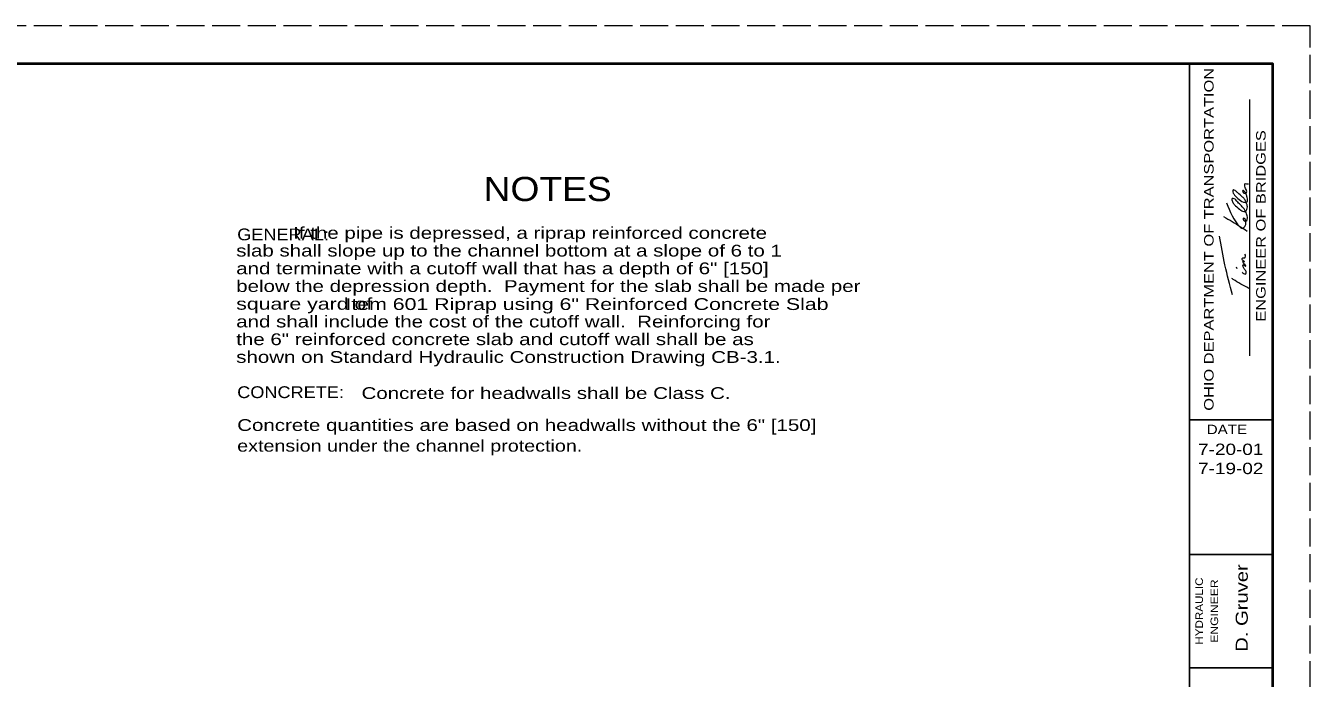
# Model space of a CAD drawing. Extents: x 685.4 to 719.4, y 1059.8 to 1105.8.
# Drawn here: x 702.44 to 719.44, y 1073.13 to 1081.77 of the extents above; entities that cross this region are included whole.
import ezdxf
from ezdxf.enums import TextEntityAlignment as Align

# ---------------------------------------------------------------- set-up
doc = ezdxf.new("R2010")
doc.units = 0
doc.header["$LTSCALE"] = 0.062
doc.linetypes.add('LONG_DASHED', pattern=[7.5, 6, -1.5])
doc.layers.add('1', color=7, linetype='Continuous', lineweight=13)

msp = doc.modelspace()

# ---------------------------------------------------------------- linework, layer by layer
at = {"layer": '1', "lineweight": 25}
for p, q in [((687.44108, 1081.27067), (718.94108, 1081.27067)), ((717.84108, 1060.27067), (717.84108, 1081.27067)), ((718.94108, 1081.27067), (718.94108, 1060.27067)), ((718.94108, 1076.55483), (717.84108, 1076.55483)), ((718.94108, 1074.77067), (717.84108, 1074.77067)), ((718.94108, 1073.27067), (717.84108, 1073.27067))]:
    msp.add_line(p, q, dxfattribs=at)
at = {"layer": '1'}
for p, q in [((718.63983, 1077.40167), (718.63983, 1080.79175)), ((718.47233, 1078.55258), (718.46217, 1078.57183))]:
    msp.add_line(p, q, dxfattribs=at)
at = {"layer": '1', "linetype": 'LONG_DASHED'}
msp.add_lwpolyline([(685.44108, 1059.77067), (719.44108, 1059.77067), (719.44108, 1081.77067), (685.44108, 1081.77067)], close=True, dxfattribs=at)
at = {"layer": '1', "lineweight": 40}
msp.add_lwpolyline([(687.44108, 1081.27067), (718.94108, 1081.27067), (718.94108, 1060.27067), (687.44108, 1060.27067)], close=True, dxfattribs=at)
at = {"layer": '1'}
for points in [[(718.33292, 1079.42767), (718.51608, 1079.09933), (718.53125, 1079.08875), (718.54142, 1079.08875), (718.57333, 1079.11242), (718.58842, 1079.14658), (718.58342, 1079.19783), (718.5665, 1079.21967), (718.553, 1079.21967), (718.55125, 1079.20667), (718.56142, 1079.1915), (718.57492, 1079.18308), (718.59, 1079.18308), (718.60517, 1079.20467), (718.60858, 1079.224), (718.59833, 1079.27933), (718.51608, 1079.39975), (718.47058, 1079.44442), (718.43367, 1079.479), (718.4085, 1079.48117), (718.41025, 1079.44258), (718.43542, 1079.40383), (718.50267, 1079.3415), (718.54475, 1079.31608), (718.57842, 1079.31158), (718.60175, 1079.33758), (718.60858, 1079.37175), (718.6035, 1079.3975), (718.57333, 1079.47067), (718.54308, 1079.50267), (718.4825, 1079.55608), (718.45383, 1079.58192), (718.42033, 1079.59717), (718.41692, 1079.56917), (718.427, 1079.54333), (718.48417, 1079.48342), (718.55483, 1079.43617), (718.60683, 1079.4385), (718.60517, 1079.49617), (718.59333, 1079.53908), (718.58, 1079.56483), (718.56983, 1079.57558), (718.54642, 1079.59058), (718.54817, 1079.5735), (718.58342, 1079.552), (718.59833, 1079.56275), (718.58525, 1079.61642), (718.57667, 1079.64433), (718.57333, 1079.657), (718.57333, 1079.66983), (718.57333, 1079.6785), (718.59833, 1079.67633), (718.62375, 1079.67633)], [(718.29408, 1079.24542), (718.51783, 1079.10792), (718.6035, 1079.05225)], [(718.41033, 1078.20842), (718.31167, 1078.60367), (718.24042, 1078.986)], [(718.54142, 1078.50733), (718.54967, 1078.49667), (718.58683, 1078.48375), (718.59158, 1078.51617), (718.5665, 1078.55258), (718.55125, 1078.58883), (718.55125, 1078.60808), (718.5665, 1078.60183), (718.57667, 1078.591), (718.58683, 1078.58667), (718.56317, 1078.61883), (718.55125, 1078.63383), (718.54817, 1078.65117), (718.57158, 1078.64458), (718.56317, 1078.65325), (718.538, 1078.68108), (718.54817, 1078.69625), (718.56492, 1078.69825), (718.57333, 1078.69625), (718.58342, 1078.71758), (718.57667, 1078.7455)], [(718.6255, 1078.29283), (718.42033, 1078.41283), (718.40475, 1078.42325)]]:
    msp.add_spline(points, degree=3, dxfattribs=at)

# ---------------------------------------------------------------- texts
for s, height, width, p in [('OHIO DEPARTMENT OF TRANSPORTATION', 0.125, 1.3, (718.161, 1078.94292)), ('ENGINEER OF BRIDGES', 0.125, 1.3, (718.84933, 1079.11971)), ('D. Gruver', 0.16, 1.25, (718.6135, 1074.06217)), ('HYDRAULIC', 0.1, 1.15, (718.02017, 1074.02175)), ('ENGINEER', 0.1, 1.2, (718.22108, 1074.02179))]:
    msp.add_text(s, height=height, rotation=90, dxfattribs=dict(at, width=width)).set_placement(p, align=Align.CENTER)
for s, height, width, p in [('NOTES', 0.32, 1.15, (708.50075, 1079.44917)), ('GENERAL:', 0.156, 1.15, (705.24017, 1078.92933)), ('          If the pipe is depressed, a riprap reinforced concrete', 0.156, 1.3, (705.22692, 1078.94967)), ('slab shall slope up to the channel bottom at a slope of 6 to 1', 0.156, 1.3, (705.22692, 1078.715)), ('and terminate with a cutoff wall that has a depth of 6" [150]', 0.156, 1.3, (705.22692, 1078.48033)), ('below the depression depth.  Payment for the slab shall be made per ', 0.156, 1.3, (705.22692, 1078.24567)), ('square yard of  ', 0.156, 1.35, (705.22692, 1078.011)), ('         Item 601 Riprap using 6" Reinforced Concrete Slab ', 0.156, 1.35, (705.9685, 1078.007)), ('and shall include the cost of the cutoff wall.  Reinforcing for ', 0.156, 1.3, (705.22692, 1077.77633)), ('the 6" reinforced concrete slab and cutoff wall shall be as', 0.156, 1.3, (705.22692, 1077.54167)), ('shown on Standard Hydraulic Construction Drawing CB-3.1.', 0.156, 1.3, (705.22692, 1077.307)), ('CONCRETE:', 0.156, 1.15, (705.24017, 1076.84108)), ('Concrete for headwalls shall be Class C.', 0.156, 1.3, (706.88533, 1076.82892)), ('Concrete quantities are based on headwalls without the 6" [150] ', 0.156, 1.3, (705.24017, 1076.40575)), ('extension under the channel protection.', 0.156, 1.25, (705.24017, 1076.13175))]:
    msp.add_text(s, height=height, dxfattribs=dict(at, width=width)).set_placement(p)
for s, height, width, p in [('DATE', 0.125, 1.2, (718.33779, 1076.36342)), ('7-20-01', 0.15, 1.25, (718.38812, 1076.08792)), ('7-19-02', 0.15, 1.25, (718.38812, 1075.83483))]:
    msp.add_text(s, height=height, dxfattribs=dict(at, width=width)).set_placement(p, align=Align.CENTER)

doc.saveas('drawing.dxf')
